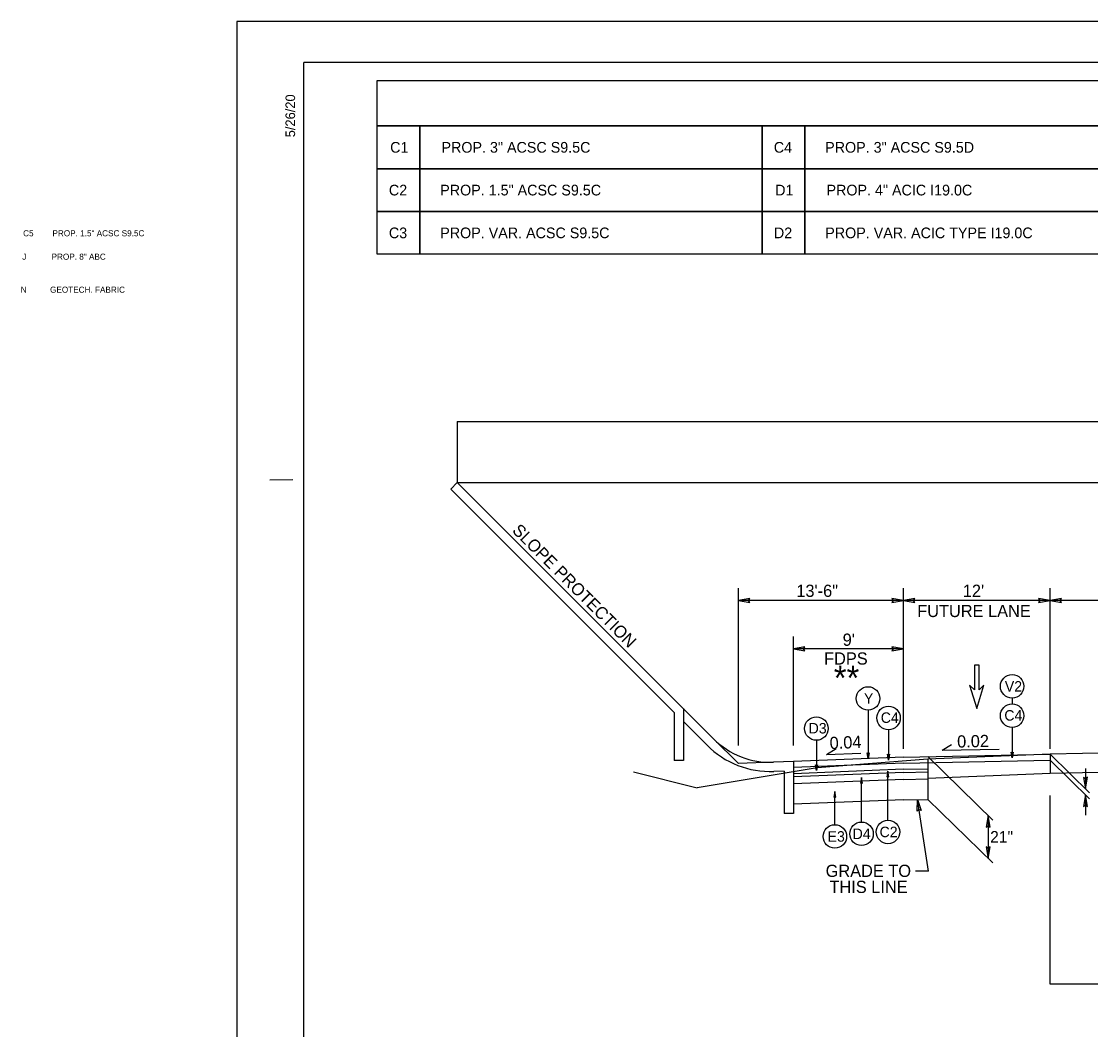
# Model space of a CAD drawing. Extents: x 1553884 to 1554215, y 810431 to 810779.
# Drawn here: x 1553883.7 to 1553971.2, y 810513.5 to 810596 of the extents above; entities that cross this region are included whole.
import ezdxf

# ---------------------------------------------------------------- set-up
doc = ezdxf.new("R2010")
doc.units = 0
for name, color, linetype in [('Old_Level_15', 7, 'Continuous'), ('Old_Level_2', 7, 'Continuous'), ('Old_Level_20', 7, 'Continuous'), ('P_RDY_Bridge_Abutment', 7, 'Continuous'), ('Prop Dimension', 7, 'Continuous'), ('Prop Hatching', 7, 'Continuous'), ('Prop Lane Arrow CELL', 7, 'Continuous'), ('Prop Shade Light', 7, 'Continuous'), ('Typical Arrow Superelevation CELL', 7, 'Continuous'), ('Typical Detail Pavement Repair CELL', 7, 'Continuous'), ('Typical Shoulder Slope CELL', 7, 'Continuous'), ('Typical Text ID Circle CELL', 7, 'Continuous')]:
    doc.layers.add(name, color=color, linetype=linetype)

msp = doc.modelspace()

# ---------------------------------------------------------------- linework, layer by layer
at = {"layer": 'Old_Level_15'}
for points in [[(1553943.325, 810548.722), (1553942.387, 810548.561), (1553943.33, 810548.394), (1553943.21, 810548.561)], [(1553954.95, 810548.4), (1553955.887, 810548.561), (1553954.945, 810548.728), (1553955.064, 810548.561)], [(1553956.825, 810548.722), (1553955.887, 810548.561), (1553956.83, 810548.394), (1553956.71, 810548.561)], [(1553966.95, 810548.4), (1553967.887, 810548.561), (1553966.945, 810548.728), (1553967.064, 810548.561)], [(1553968.825, 810548.722), (1553967.887, 810548.561), (1553968.83, 810548.394), (1553968.71, 810548.561)], [(1553947.825, 810544.77), (1553946.887, 810544.609), (1553947.83, 810544.442), (1553947.71, 810544.609)], [(1553954.95, 810544.447), (1553955.887, 810544.609), (1553954.945, 810544.776), (1553955.064, 810544.609)], [(1553953.08, 810536.107), (1553952.999, 810535.638), (1553952.916, 810536.109), (1553952.999, 810536.05)], [(1553954.754, 810535.978), (1553954.673, 810535.509), (1553954.59, 810535.98), (1553954.673, 810535.92)], [(1553964.866, 810536.163), (1553964.785, 810535.694), (1553964.702, 810536.165), (1553964.785, 810536.106)], [(1553948.854, 810535.111), (1553948.773, 810534.643), (1553948.69, 810535.114), (1553948.773, 810535.054)], [(1553954.71, 810534.128), (1553954.629, 810534.597), (1553954.546, 810534.126), (1553954.629, 810534.186)], [(1553952.546, 810533.609), (1553952.465, 810534.078), (1553952.382, 810533.607), (1553952.465, 810533.667)], [(1553970.625, 810534.095), (1553970.786, 810533.157), (1553970.953, 810534.1), (1553970.786, 810533.98)], [(1553950.365, 810532.476), (1553950.285, 810532.945), (1553950.201, 810532.474), (1553950.285, 810532.534)], [(1553957.022, 810531.326), (1553957.041, 810532.277), (1553957.347, 810531.37), (1553957.164, 810531.463)], [(1553970.948, 810531.72), (1553970.786, 810532.657), (1553970.62, 810531.715), (1553970.786, 810531.834)], [(1553962.988, 810530.024), (1553962.826, 810530.962), (1553962.659, 810530.019), (1553962.826, 810530.139)], [(1553962.665, 810528.399), (1553962.826, 810527.462), (1553962.993, 810528.404), (1553962.826, 810528.284)]]:
    msp.add_lwpolyline(points, close=True, dxfattribs=at)
at = {"layer": 'Old_Level_2'}
for p, q in [((1553906.821, 810434.329), (1553906.825, 810592.576)), ((1554154.325, 810592.576), (1553906.825, 810592.576)), ((1553904.051, 810558.452), (1553905.928, 810558.456))]:
    msp.add_line(p, q, dxfattribs=at)
at = {"layer": 'Old_Level_20'}
for p, q in [((1553957.887, 810535.594), (1553948.841, 810534.87)), ((1553967.887, 810535.994), (1553957.887, 810535.594)), ((1553957.887, 810535.794), (1553963.205, 810530.591)), ((1553957.887, 810535.594), (1553957.887, 810534.009)), ((1553979.887, 810536.234), (1553967.887, 810535.994)), ((1553967.887, 810535.994), (1553967.887, 810534.409)), ((1553967.887, 810535.994), (1553971.123, 810532.828)), ((1553967.887, 810535.494), (1553971.123, 810532.328)), ((1553948.841, 810534.87), (1553939.014, 810533.232)), ((1553979.887, 810534.649), (1553967.887, 810534.409)), ((1553970.786, 810534.824), (1553970.786, 810533.157)), ((1553933.803, 810534.535), (1553939.014, 810533.232)), ((1553967.887, 810534.409), (1553957.887, 810534.009)), ((1553957.887, 810532.294), (1553963.205, 810527.091)), ((1553970.786, 810532.657), (1553970.786, 810530.991)), ((1553962.826, 810530.962), (1553962.826, 810527.462))]:
    msp.add_line(p, q, dxfattribs=at)
at = {"layer": 'P_RDY_Bridge_Abutment'}
for p, q in [((1553919.386, 810563.217), (1554123.308, 810563.217)), ((1553919.386, 810563.217), (1553919.386, 810558.217)), ((1553919.386, 810558.217), (1553918.856, 810557.686)), ((1553940.354, 810537.249), (1553919.386, 810558.217)), ((1553919.386, 810558.217), (1554123.308, 810558.217)), ((1553937.137, 810539.405), (1553918.856, 810557.686)), ((1553937.137, 810539.405), (1553937.137, 810535.474)), ((1553937.887, 810539.716), (1553937.887, 810535.474)), ((1553939.824, 810536.719), (1553937.887, 810538.655)), ((1553942.387, 810535.216), (1553940.354, 810537.249)), ((1553937.887, 810535.474), (1553937.137, 810535.474)), ((1553945.261, 810535.329), (1553942.387, 810535.216)), ((1553946.887, 810535.394), (1553945.261, 810535.329)), ((1553946.137, 810534.613), (1553945.29, 810534.58)), ((1553946.137, 810534.613), (1553946.137, 810531.138)), ((1553946.887, 810535.394), (1553946.887, 810531.138)), ((1553946.887, 810531.138), (1553946.137, 810531.138))]:
    msp.add_line(p, q, dxfattribs=at)
for radius in [6.572, 7.322]:
    msp.add_arc((1553945.001, 810541.896), radius, 225, 272.26207, dxfattribs=at)
at = {"layer": 'Prop Dimension'}
for points in [[(1553912.825, 810591.115), (1554133.325, 810591.115), (1554133.325, 810587.396), (1553912.825, 810587.396)], [(1553912.825, 810587.396), (1553916.325, 810587.396), (1553916.325, 810583.896), (1553912.825, 810583.896)], [(1553916.325, 810587.396), (1553944.325, 810587.396), (1553944.325, 810583.896), (1553916.325, 810583.896)], [(1553944.325, 810587.396), (1553947.825, 810587.396), (1553947.825, 810583.896), (1553944.325, 810583.896)], [(1553947.825, 810587.396), (1553975.825, 810587.396), (1553975.825, 810583.896), (1553947.825, 810583.896)], [(1553912.825, 810583.896), (1553916.325, 810583.896), (1553916.325, 810580.396), (1553912.825, 810580.396)], [(1553916.325, 810583.896), (1553944.325, 810583.896), (1553944.325, 810580.396), (1553916.325, 810580.396)], [(1553944.325, 810583.896), (1553947.825, 810583.896), (1553947.825, 810580.396), (1553944.325, 810580.396)], [(1553947.825, 810583.896), (1553975.825, 810583.896), (1553975.825, 810580.396), (1553947.825, 810580.396)], [(1553912.825, 810580.396), (1553916.325, 810580.396), (1553916.325, 810576.896), (1553912.825, 810576.896)], [(1553916.325, 810580.396), (1553944.325, 810580.396), (1553944.325, 810576.896), (1553916.325, 810576.896)], [(1553944.325, 810580.396), (1553947.825, 810580.396), (1553947.825, 810576.896), (1553944.325, 810576.896)], [(1553947.825, 810580.396), (1553975.825, 810580.396), (1553975.825, 810576.896), (1553947.825, 810576.896)]]:
    msp.add_lwpolyline(points, close=True, dxfattribs=at)
at = {"layer": 'Prop Hatching'}
for p, q in [((1553967.887, 810517.168), (1553967.887, 810532.618)), ((1553982.357, 810517.168), (1553967.887, 810517.168))]:
    msp.add_line(p, q, dxfattribs=at)
msp.add_lwpolyline([(1553962.481, 810541.635), (1553962.075, 810541.26), (1553962.075, 810543.26), (1553961.7, 810543.26), (1553961.7, 810541.26), (1553961.294, 810541.635), (1553961.887, 810539.729)], close=True, dxfattribs=at)
at = {"layer": 'Prop Lane Arrow CELL'}
for p, q in [((1554156.35, 810595.951), (1553901.353, 810595.951)), ((1553901.353, 810595.951), (1553901.353, 810430.954))]:
    msp.add_line(p, q, dxfattribs=at)
at = {"layer": 'Prop Shade Light'}
for p, q in [((1553955.887, 810535.754), (1553946.887, 810535.394)), ((1553955.887, 810535.754), (1553967.887, 810535.994)), ((1553955.887, 810535.254), (1553967.887, 810535.494)), ((1553955.887, 810535.254), (1553946.887, 810534.894)), ((1553955.887, 810534.754), (1553946.887, 810534.394)), ((1553955.887, 810534.754), (1553957.887, 810534.794)), ((1553955.887, 810534.504), (1553946.887, 810534.144)), ((1553955.887, 810533.92), (1553946.887, 810533.56)), ((1553955.887, 810534.504), (1553957.887, 810534.544)), ((1553955.887, 810533.92), (1553957.887, 810533.96)), ((1553957.887, 810534.009), (1553957.887, 810532.294)), ((1553955.887, 810532.254), (1553946.887, 810531.894)), ((1553955.887, 810532.254), (1553957.887, 810532.294))]:
    msp.add_line(p, q, dxfattribs=at)
at = {"layer": 'Typical Arrow Superelevation CELL'}
for p, q in [((1553942.387, 810536.7), (1553942.387, 810549.561)), ((1553946.887, 810536.709), (1553946.887, 810545.609)), ((1553949.606, 810535.971), (1553950.38, 810536.46)), ((1553959.055, 810536.309), (1553959.838, 810536.783)), ((1553959.055, 810536.309), (1553963.715, 810536.403)), ((1553949.606, 810535.971), (1553952.401, 810536.083)), ((1553957.93, 810526.417), (1553957.041, 810532.277)), ((1553957.93, 810526.417), (1553956.87, 810526.417))]:
    msp.add_line(p, q, dxfattribs=at)
at = {"layer": 'Typical Shoulder Slope CELL'}
for p, q in [((1553955.887, 810536.439), (1553955.887, 810549.561)), ((1553967.887, 810536.439), (1553967.887, 810549.561)), ((1553955.887, 810548.561), (1553942.387, 810548.561)), ((1553967.887, 810548.561), (1553955.887, 810548.561)), ((1553979.887, 810548.561), (1553967.887, 810548.561)), ((1553955.887, 810544.609), (1553946.887, 810544.609))]:
    msp.add_line(p, q, dxfattribs=at)
at = {"layer": 'Typical Text ID Circle CELL'}
for p, q in [((1553964.785, 810540.58), (1553964.785, 810540.103)), ((1553952.999, 810539.59), (1553952.999, 810535.638)), ((1553964.785, 810538.18), (1553964.785, 810535.694)), ((1553954.673, 810537.994), (1553954.673, 810535.509)), ((1553948.773, 810537.128), (1553948.773, 810534.643)), ((1553954.629, 810530.589), (1553954.629, 810534.597)), ((1553952.465, 810530.438), (1553952.465, 810534.078)), ((1553950.285, 810530.22), (1553950.285, 810532.945))]:
    msp.add_line(p, q, dxfattribs=at)
for centre in [(1553964.785, 810541.542), (1553952.999, 810540.552), (1553954.673, 810538.956), (1553964.785, 810539.141), (1553948.773, 810538.089), (1553950.285, 810529.259), (1553952.465, 810529.477), (1553954.629, 810529.628)]:
    msp.add_circle(centre, 0.962, dxfattribs=at)

# ---------------------------------------------------------------- texts
at = {"layer": 'Old_Level_2'}
msp.add_text('5/26/20', height=0.7875, rotation=90, dxfattribs=at).set_placement((1553906.123, 810586.466))
at = {"layer": 'Old_Level_20'}
msp.add_text('21"', height=0.9558, dxfattribs=at).set_placement((1553962.985, 810528.744))
at = {"layer": 'Prop Dimension'}
for s, height, p in [('C1', 0.875, (1553913.9, 810585.208)), ('PROP. 3" ACSC S9.5C', 0.875, (1553918.1, 810585.208)), ('C4', 0.875, (1553945.288, 810585.208)), ('PROP. 3" ACSC S9.5D', 0.875, (1553949.488, 810585.208)), ('C2', 0.875, (1553913.795, 810581.708)), ('PROP. 1.5" ACSC S9.5C', 0.875, (1553917.995, 810581.708)), ('D1', 0.875, (1553945.4, 810581.708)), ('PROP. 4" ACIC I19.0C', 0.875, (1553949.6, 810581.708)), ('C5', 0.5, (1553883.871, 810578.365)), ('PROP. 1.5" ACSC S9.5C', 0.5, (1553886.271, 810578.365)), ('C3', 0.875, (1553913.795, 810578.208)), ('PROP. VAR. ACSC S9.5C', 0.875, (1553917.995, 810578.208)), ('D2', 0.875, (1553945.295, 810578.208)), ('PROP. VAR. ACIC TYPE I19.0C', 0.875, (1553949.495, 810578.208)), ('J', 0.5, (1553883.798, 810576.446)), ('PROP. 8" ABC', 0.5, (1553886.198, 810576.446)), ('N', 0.5, (1553883.673, 810573.747)), ('GEOTECH. FABRIC', 0.5, (1553886.073, 810573.747))]:
    msp.add_text(s, height=height, dxfattribs=at).set_placement(p)
at = {"layer": 'Typical Arrow Superelevation CELL'}
for s, rotation, p in [('SLOPE PROTECTION', 315, (1553923.817, 810554.227)), ('0.04', 2.29061, (1553949.875, 810536.4)), ('0.02', 1.14587, (1553960.296, 810536.526))]:
    msp.add_text(s, height=1, rotation=rotation, dxfattribs=at).set_placement(p)
for s, height, p in [('13\'-6"', 1, (1553947.131, 810548.861)), ("12'", 1, (1553960.75, 810548.861)), ('FUTURE LANE', 1, (1553957.021, 810547.209)), ("9'", 1, (1553950.922, 810544.857)), ('FDPS', 1, (1553949.399, 810543.319)), ('**', 2, (1553950.197, 810541.234)), ('GRADE TO ', 1, (1553949.529, 810525.944)), ('THIS LINE', 1, (1553949.841, 810524.633))]:
    msp.add_text(s, height=height, dxfattribs=at).set_placement(p)
at = {"layer": 'Typical Detail Pavement Repair CELL'}
for s, height, p in [('V2', 0.8608, (1553964.189, 810541.108)), ('Y', 0.861, (1553952.663, 810540.121)), ('C4', 0.8608, (1553954.038, 810538.549)), ('C4', 0.8608, (1553964.15, 810538.735)), ('D3', 0.8608, (1553948.139, 810537.683)), ('E3', 0.8608, (1553949.689, 810528.829)), ('D4', 0.8608, (1553951.739, 810529.046)), ('C2', 0.8608, (1553953.943, 810529.197))]:
    msp.add_text(s, height=height, dxfattribs=at).set_placement(p)

doc.saveas('drawing.dxf')
